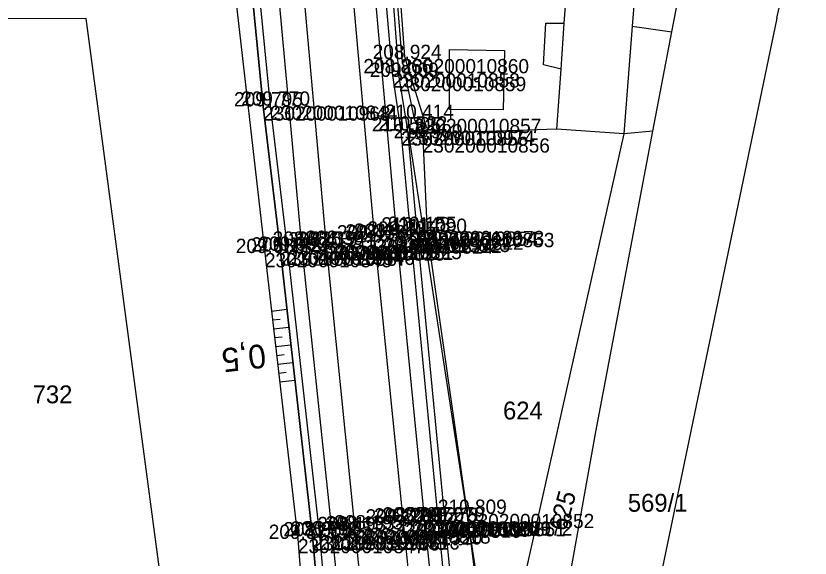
# Model space of a CAD drawing. Extents: x -563148 to -561712, y -1182311 to -1179502.
# Drawn here: x -562591.4 to -562524.5, y -1180944.5 to -1180898.9 of the extents above; entities that cross this region are included whole.
import ezdxf

# ---------------------------------------------------------------- set-up
doc = ezdxf.new("R2010")
doc.units = 0
for name, color, linetype in [('Vrstva 1', 7, 'Continuous'), ('Vrstva 13', 7, 'Continuous'), ('Vrstva 23', 7, 'Continuous'), ('Vrstva 4', 7, 'Continuous'), ('Vrstva 48', 7, 'Continuous'), ('Vrstva 49', 7, 'Continuous'), ('Vrstva 53', 7, 'Continuous'), ('Vrstva 55', 7, 'Continuous'), ('Vrstva 56', 7, 'Continuous'), ('Vrstva 57', 7, 'Continuous'), ('Vrstva 60', 7, 'Continuous'), ('Vrstva 61', 7, 'Continuous')]:
    doc.layers.add(name, color=color, linetype=linetype)

msp = doc.modelspace()

# ---------------------------------------------------------------- linework, layer by layer
at = {"layer": 'Vrstva 1'}
for points in [[(-562568.447, -1180769.256), (-562569.304, -1180793.968), (-562569.923, -1180820.538), (-562569.851, -1180844.577), (-562569.048, -1180868.505), (-562567.339, -1180894.985), (-562565.256, -1180918.218), (-562562.828, -1180942.165), (-562560.347, -1180966.087), (-562558.006, -1180988.683), (-562555.657, -1181011.477), (-562554.518, -1181022.359), (-562552.403, -1181042.927), (-562550.106, -1181065.457), (-562547.968, -1181086.047), (-562545.847, -1181106.654), (-562542.313, -1181141.048), (-562539.775, -1181165.619)], [(-562564.303, -1180769.263), (-562565.158, -1180794.441), (-562565.748, -1180820.49), (-562565.701, -1180844.542), (-562564.942, -1180867.892), (-562563.243, -1180894.349), (-562561.18, -1180917.623), (-562558.766, -1180941.515), (-562556.288, -1180965.419), (-562553.951, -1180988.015), (-562551.606, -1181010.711), (-562550.463, -1181021.746), (-562548.34, -1181042.363), (-562545.995, -1181064.902), (-562543.875, -1181085.505), (-562541.786, -1181105.972), (-562538.225, -1181140.466), (-562535.703, -1181164.996)]]:
    msp.add_lwpolyline(points, dxfattribs=at)
at = {"layer": 'Vrstva 13'}
for points in [[(-562557.976, -1181010.58), (-562558, -1181010.307), (-562558.079, -1181009.424), (-562559.927, -1180988.799), (-562562.266, -1180966.351), (-562564.717, -1180942.596), (-562567.303, -1180918.218), (-562569.432, -1180894.97), (-562570.95, -1180868.529), (-562571.576, -1180844.614), (-562571.801, -1180820.205), (-562571.006, -1180793.955), (-562570.112, -1180769.35), (-562569.341, -1180744.38), (-562569.271, -1180721.9), (-562569.501, -1180697.948), (-562571.023, -1180670.137), (-562572.171, -1180659.346), (-562572.635, -1180659.406), (-562573.467, -1180659.616), (-562573.33, -1180660.858)], [(-562561.149, -1181009.131), (-562561.24, -1181008.764), (-562559.947, -1181008.525), (-562560.154, -1181006.289), (-562562.147, -1180984.227), (-562564.005, -1180966.506), (-562565.277, -1180955.253), (-562566.403, -1180942.673), (-562569.1, -1180918.713), (-562570.551, -1180906.501), (-562571.678, -1180895.015), (-562572.932, -1180869.607), (-562573.483, -1180850.031), (-562573.549, -1180847.711), (-562573.649, -1180844.142), (-562573.538, -1180836.828), (-562574.031, -1180828.645), (-562574.084, -1180821.529), (-562574.422, -1180808.724), (-562574.116, -1180795.427), (-562573.88, -1180788.802), (-562572.624, -1180769.58)], [(-562572.217, -1180769.564), (-562573.373, -1180788.797), (-562573.562, -1180795.348), (-562573.924, -1180808.763), (-562573.634, -1180821.501), (-562573.47, -1180828.715), (-562572.964, -1180836.872), (-562573.105, -1180844.114), (-562572.333, -1180869.578), (-562571.079, -1180894.971), (-562569.955, -1180906.437), (-562568.504, -1180918.644), (-562565.806, -1180942.613), (-562564.68, -1180955.193), (-562563.435, -1180966.477), (-562561.225, -1180988.666), (-562559.67, -1181006.209), (-562559.413, -1181008.813), (-562561.149, -1181009.131)], [(-562561.397, -1180873.968), (-562559.12, -1180904.019), (-562558.4, -1180908.534), (-562557.605, -1180916.976), (-562555.246, -1180941.421), (-562552.956, -1180964.817), (-562550.774, -1180987.416), (-562548.526, -1181008.985), (-562550.049, -1181009.182), (-562550.096, -1181008.72), (-562549.609, -1181008.671), (-562548.981, -1181008.59), (-562551.206, -1180988.11), (-562553.503, -1180964.871), (-562555.793, -1180941.474), (-562558.153, -1180917.028), (-562558.946, -1180908.6), (-562559.663, -1180903.711), (-562560.701, -1180891.906)]]:
    msp.add_lwpolyline(points, dxfattribs=at)
at = {"layer": 'Vrstva 23'}
msp.add_lwpolyline([(-562560.511, -1180866.54), (-562560.868, -1180873.926), (-562559.697, -1180892.393), (-562558.883, -1180902.514), (-562557.847, -1180907.545)], dxfattribs=at)
at = {"layer": 'Vrstva 4'}
for points in [[(-562548.401, -1181107.417), (-562550.317, -1181086.48), (-562552.348, -1181066.066), (-562554.262, -1181043.149), (-562556.331, -1181022.59), (-562557.976, -1181010.58), (-562558, -1181010.307), (-562558.079, -1181009.424), (-562559.927, -1180988.799), (-562562.266, -1180966.351), (-562564.717, -1180942.596), (-562567.303, -1180918.218), (-562569.432, -1180894.97), (-562570.95, -1180868.529), (-562571.576, -1180844.614), (-562571.801, -1180820.205), (-562571.006, -1180793.955), (-562570.112, -1180769.35), (-562569.341, -1180744.38), (-562569.271, -1180721.9), (-562569.501, -1180697.948), (-562571.023, -1180670.137), (-562572.171, -1180659.346)], [(-562561.997, -1180660.623), (-562561.57, -1180669.053), (-562560.795, -1180699.571), (-562561.474, -1180721.983), (-562562.677, -1180769.239), (-562563.536, -1180794.555), (-562563.999, -1180820.485), (-562563.902, -1180844.088), (-562563.277, -1180867.211), (-562561.411, -1180894.209), (-562559.327, -1180917.369), (-562556.979, -1180941.413), (-562554.469, -1180965.098), (-562552.194, -1180988.078), (-562550.096, -1181008.72), (-562550.049, -1181009.182), (-562549.687, -1181012.277), (-562549.184, -1181015.02), (-562548.066, -1181022.403), (-562546.039, -1181042.458), (-562543.415, -1181064.622), (-562541.447, -1181085.622), (-562540.154, -1181099.369), (-562539.809, -1181101.815)]]:
    msp.add_lwpolyline(points, dxfattribs=at)
at = {"layer": 'Vrstva 48'}
for p, q in [((-562569.841, -1180923.723), (-562568.553, -1180923.574)), ((-562569.755, -1180924.468), (-562569.112, -1180924.394)), ((-562569.669, -1180925.213), (-562568.385, -1180925.065)), ((-562569.583, -1180925.958), (-562568.942, -1180925.884)), ((-562569.497, -1180926.703), (-562568.217, -1180926.555)), ((-562569.411, -1180927.448), (-562568.772, -1180927.374)), ((-562569.325, -1180928.193), (-562568.049, -1180928.046)), ((-562569.239, -1180928.938), (-562568.602, -1180928.865)), ((-562569.153, -1180929.683), (-562567.882, -1180929.537))]:
    msp.add_line(p, q, dxfattribs=at)
at = {"layer": 'Vrstva 49'}
for points in [[(-562572.624, -1180769.58), (-562573.88, -1180788.802), (-562574.116, -1180795.427), (-562574.422, -1180808.724), (-562574.084, -1180821.529), (-562574.031, -1180828.645), (-562573.538, -1180836.828), (-562573.649, -1180844.142), (-562573.549, -1180847.711), (-562573.483, -1180850.031), (-562572.932, -1180869.607), (-562571.678, -1180895.015), (-562570.551, -1180906.501), (-562569.1, -1180918.713), (-562566.403, -1180942.673), (-562565.277, -1180955.253), (-562564.005, -1180966.506), (-562562.147, -1180984.227), (-562560.154, -1181006.289), (-562559.947, -1181008.525), (-562561.24, -1181008.764)], [(-562575.801, -1180850.097), (-562574.274, -1180870.757), (-562573.123, -1180895.103), (-562570.405, -1180918.84), (-562567.628, -1180942.893), (-562565.837, -1180965.772), (-562563.388, -1180986.541), (-562561.24, -1181008.764)], [(-562557.847, -1180907.545), (-562557.125, -1180909.188), (-562556.747, -1180917.145), (-562553.393, -1180940.785), (-562550.397, -1180964.507), (-562549.891, -1180969.335)]]:
    msp.add_lwpolyline(points, dxfattribs=at)
at = {"layer": 'Vrstva 53'}
for p, q in [((-562559.38, -1180892.38), (-562558.65, -1180902.29)), ((-562585.46, -1180899.1), (-562596.76, -1180899.17)), ((-562577.26, -1180960.65), (-562585.46, -1180899.1)), ((-562558.65, -1180902.29), (-562556.81, -1180908.3)), ((-562556.81, -1180908.3), (-562558.33, -1180908.84)), ((-562558.33, -1180908.84), (-562550.94, -1180956.71))]:
    msp.add_line(p, q, dxfattribs=at)
at = {"layer": 'Vrstva 55'}
for p, q in [((-562536.15, -1180900.24), (-562532.93, -1180883.47)), ((-562527.31, -1180899.09), (-562524.51, -1180886.75)), ((-562527.31, -1180899.09), (-562539.96, -1180959.85)), ((-562537.74, -1180908.59), (-562536.15, -1180900.24)), ((-562545.82, -1180908.43), (-562558.33, -1180908.84)), ((-562540.2, -1180908.81), (-562545.82, -1180908.43)), ((-562542.56, -1180933.87), (-562537.74, -1180908.59)), ((-562537.74, -1180908.59), (-562540.2, -1180908.81)), ((-562540.2, -1180908.81), (-562550.94, -1180956.71)), ((-562546.01, -1180953.12), (-562542.56, -1180933.87))]:
    msp.add_line(p, q, dxfattribs=at)
at = {"layer": 'Vrstva 56'}
for p, q in [((-562538.19, -1180883.04), (-562539.49, -1180899.74)), ((-562545.21, -1180899.5), (-562544.9, -1180895.7)), ((-562546.94, -1180903.01), (-562546.76, -1180899.51)), ((-562546.76, -1180899.51), (-562545.21, -1180899.5)), ((-562545.47, -1180903.37), (-562545.21, -1180899.5)), ((-562539.49, -1180899.74), (-562540.2, -1180908.81)), ((-562539.49, -1180899.74), (-562536.15, -1180900.24)), ((-562554.88, -1180906.76), (-562554.86, -1180901.7)), ((-562554.86, -1180901.7), (-562550.25, -1180901.81)), ((-562550.25, -1180901.81), (-562550.36, -1180906.78)), ((-562545.47, -1180903.37), (-562546.94, -1180903.01)), ((-562545.82, -1180908.43), (-562545.47, -1180903.37)), ((-562550.36, -1180906.78), (-562554.88, -1180906.76))]:
    msp.add_line(p, q, dxfattribs=at)
at = {"layer": 'Vrstva 57'}
msp.add_circle((-562552.579, -1180904.26), 0.175, dxfattribs=at)
at = {"layer": 'Vrstva 60'}
for p, q in [((-562558.883, -1180902.514), (-562558.883, -1180902.514)), ((-562559.663, -1180903.711), (-562559.663, -1180903.711)), ((-562559.12, -1180904.019), (-562559.12, -1180904.019)), ((-562570.551, -1180906.501), (-562570.551, -1180906.501)), ((-562569.955, -1180906.437), (-562569.955, -1180906.437)), ((-562557.847, -1180907.545), (-562557.847, -1180907.545)), ((-562558.946, -1180908.6), (-562558.946, -1180908.6)), ((-562558.4, -1180908.534), (-562558.4, -1180908.534)), ((-562557.125, -1180909.188), (-562557.125, -1180909.188)), ((-562559.327, -1180917.369), (-562559.327, -1180917.369)), ((-562558.153, -1180917.028), (-562558.153, -1180917.028)), ((-562557.605, -1180916.976), (-562557.605, -1180916.976)), ((-562556.747, -1180917.145), (-562556.747, -1180917.145)), ((-562561.893, -1180917.692), (-562561.893, -1180917.692)), ((-562561.18, -1180917.623), (-562561.18, -1180917.623)), ((-562560.466, -1180917.554), (-562560.466, -1180917.554)), ((-562569.1, -1180918.713), (-562569.1, -1180918.713)), ((-562568.504, -1180918.644), (-562568.504, -1180918.644)), ((-562567.303, -1180918.218), (-562567.303, -1180918.218)), ((-562565.974, -1180918.28), (-562565.974, -1180918.28)), ((-562565.256, -1180918.218), (-562565.256, -1180918.218)), ((-562564.539, -1180918.156), (-562564.539, -1180918.156)), ((-562570.405, -1180918.84), (-562570.405, -1180918.84)), ((-562553.393, -1180940.785), (-562553.393, -1180940.785)), ((-562558.766, -1180941.515), (-562558.766, -1180941.515)), ((-562558.056, -1180941.432), (-562558.056, -1180941.432)), ((-562556.979, -1180941.413), (-562556.979, -1180941.413)), ((-562555.793, -1180941.474), (-562555.793, -1180941.474)), ((-562555.246, -1180941.421), (-562555.246, -1180941.421)), ((-562562.828, -1180942.165), (-562562.828, -1180942.165)), ((-562562.116, -1180942.091), (-562562.116, -1180942.091)), ((-562559.476, -1180941.598), (-562559.476, -1180941.598)), ((-562566.403, -1180942.673), (-562566.403, -1180942.673)), ((-562565.806, -1180942.613), (-562565.806, -1180942.613)), ((-562564.717, -1180942.596), (-562564.717, -1180942.596)), ((-562563.539, -1180942.239), (-562563.539, -1180942.239)), ((-562567.628, -1180942.893), (-562567.628, -1180942.893))]:
    msp.add_line(p, q, dxfattribs=at)

# ---------------------------------------------------------------- texts
at = {"layer": 'Vrstva 48'}
msp.add_text('0,5', height=2, rotation=186.58583, dxfattribs=at).set_placement((-562570.446, -1180926.476))
at = {"layer": 'Vrstva 57'}
for s, p in [('732', (-562589.959, -1180931.48)), ('624', (-562550.362, -1180932.84)), ('569/1', (-562539.854, -1180940.605))]:
    msp.add_text(s, height=1.5, dxfattribs=at).set_placement(p)
msp.add_text('625', height=1.5, rotation=74.38761, dxfattribs=at).set_placement((-562545.091, -1180942.326))
at = {"layer": 'Vrstva 60'}
for s, p in [('230200010860', (-562558.883, -1180903.714)), ('230200010858', (-562559.663, -1180904.911)), ('230200010859', (-562559.12, -1180905.219)), ('230200010968', (-562570.551, -1180907.701)), ('230200010844', (-562569.955, -1180907.637)), ('230200010857', (-562557.847, -1180908.745)), ('230200010855', (-562558.946, -1180909.8)), ('230200010974', (-562558.4, -1180909.734)), ('230200010856', (-562557.125, -1180910.388)), ('230200010822', (-562559.327, -1180918.569)), ('230200010854', (-562558.153, -1180918.228)), ('230200010973', (-562557.605, -1180918.176)), ('230200010853', (-562556.747, -1180918.345)), ('230200010825', (-562564.539, -1180919.356)), ('230200010824', (-562561.893, -1180918.892)), ('230200011522', (-562561.18, -1180918.823)), ('230200010823', (-562560.466, -1180918.754)), ('230200010967', (-562569.1, -1180919.913)), ('230200010846', (-562568.504, -1180919.844)), ('230200010827', (-562567.303, -1180919.418)), ('230200010826', (-562565.974, -1180919.48)), ('230200011521', (-562565.256, -1180919.418)), ('230200010845', (-562570.405, -1180920.04)), ('230200010852', (-562553.393, -1180941.985)), ('230200011519', (-562558.766, -1180942.715)), ('230200010820', (-562558.056, -1180942.632)), ('230200010821', (-562556.979, -1180942.613)), ('230200010851', (-562555.793, -1180942.674)), ('230200010972', (-562555.246, -1180942.621)), ('230200011520', (-562562.828, -1180943.365)), ('230200010818', (-562562.116, -1180943.291)), ('230200010819', (-562559.476, -1180942.798)), ('230200010847', (-562567.628, -1180944.093)), ('230200010966', (-562566.403, -1180943.873)), ('230200010848', (-562565.806, -1180943.813)), ('230200010816', (-562564.717, -1180943.796)), ('230200010817', (-562563.539, -1180943.439))]:
    msp.add_text(s, height=1.2, dxfattribs=at).set_placement(p)
at = {"layer": 'Vrstva 61'}
for s, p in [('208.924', (-562561.334, -1180902.514)), ('208.866', (-562562.115, -1180903.711)), ('209.009', (-562561.574, -1180904.019)), ('209.795', (-562573.007, -1180906.501)), ('209.770', (-562572.406, -1180906.437)), ('210.414', (-562560.298, -1180907.545)), ('210.505', (-562561.402, -1180908.6)), ('210.522', (-562560.848, -1180908.534)), ('210.900', (-562559.576, -1180909.188)), ('210.148', (-562560.607, -1180917.028)), ('210.155', (-562560.061, -1180916.976)), ('211.090', (-562559.198, -1180917.145)), ('208.433', (-562564.345, -1180917.692)), ('208.414', (-562563.631, -1180917.623)), ('208.414', (-562562.917, -1180917.554)), ('208.235', (-562561.783, -1180917.369)), ('209.090', (-562570.955, -1180918.644)), ('208.226', (-562569.755, -1180918.218)), ('208.415', (-562568.43, -1180918.28)), ('208.394', (-562567.707, -1180918.218)), ('208.394', (-562566.99, -1180918.156)), ('209.666', (-562572.857, -1180918.84)), ('209.142', (-562571.548, -1180918.713)), ('207.956', (-562559.431, -1180941.413)), ('209.279', (-562557.7, -1180941.421)), ('210.809', (-562555.847, -1180940.785)), ('208.195', (-562564.572, -1180942.091)), ('208.205', (-562561.932, -1180941.598)), ('208.205', (-562561.222, -1180941.515)), ('208.207', (-562560.508, -1180941.432)), ('209.275', (-562558.249, -1180941.474)), ('208.850', (-562568.854, -1180942.673)), ('208.792', (-562568.254, -1180942.613)), ('207.985', (-562567.173, -1180942.596)), ('208.193', (-562565.991, -1180942.239)), ('208.193', (-562565.28, -1180942.165)), ('209.379', (-562570.082, -1180942.893))]:
    msp.add_text(s, height=1.2, dxfattribs=at).set_placement(p)

doc.saveas('drawing.dxf')
